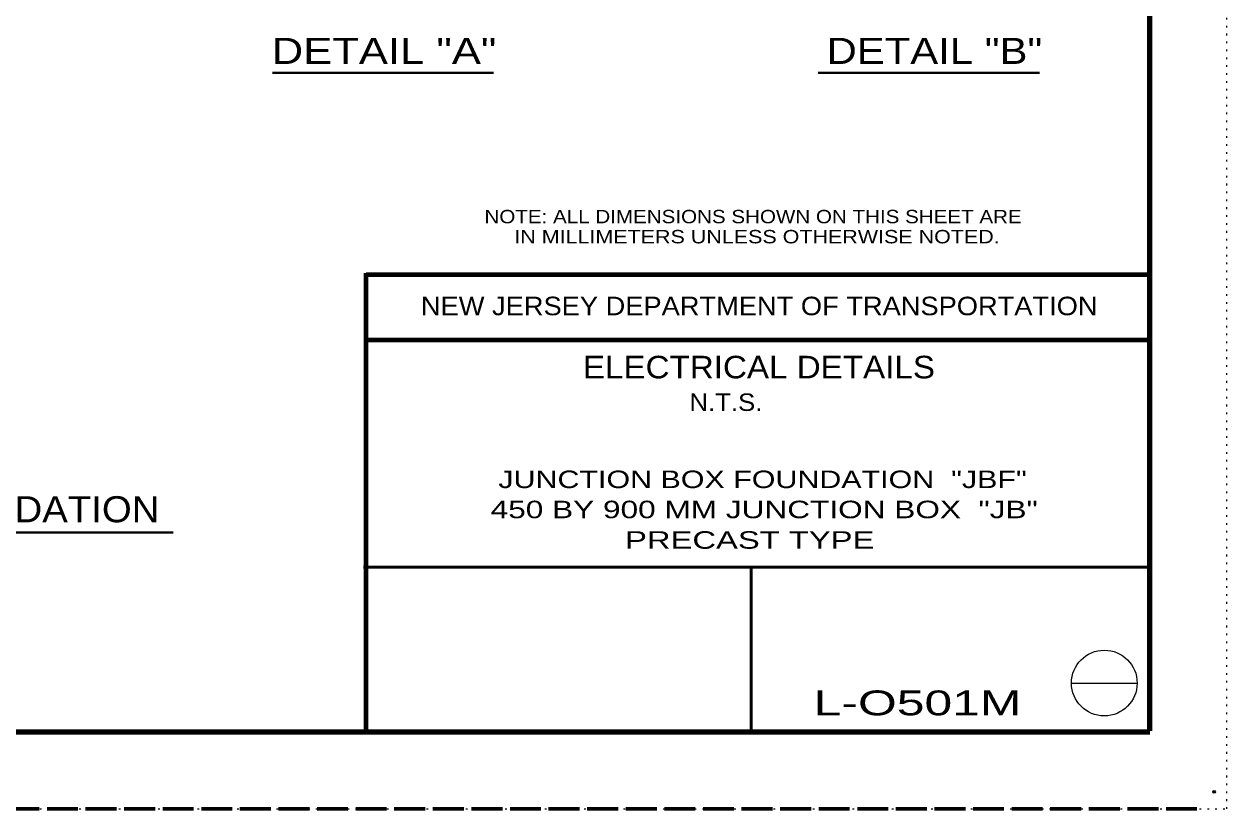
# Model space of a CAD drawing. Extents: x 312583 to 312854, y 144419 to 144597.
# Drawn here: x 312783.4 to 312853.5, y 144418.6 to 144464.3 of the extents above; entities that cross this region are included whole.
import ezdxf
from ezdxf.enums import TextEntityAlignment as Align

# ---------------------------------------------------------------- set-up
doc = ezdxf.new("R2010")
doc.units = 0
doc.header["$LTSCALE"] = 0.3
doc.header["$PDMODE"] = 32
doc.header["$PDSIZE"] = 0.15
doc.linetypes.add('DOTTED', pattern=[1.5, 0.3, -1.2])
doc.linetypes.add('LONG_DASHED', pattern=[7.5, 6, -1.5])
for name, color, linetype, lineweight in [('1', 7, 'Continuous', 25), ('10', 7, 'Continuous', 25), ('2', 7, 'Continuous', 13), ('63', 7, 'DOTTED', 13)]:
    doc.layers.add(name, color=color, linetype=linetype, lineweight=lineweight)
doc.layers.add('5', color=7, linetype='Continuous')

msp = doc.modelspace()

# ---------------------------------------------------------------- linework, layer by layer
at = {"layer": '1', "lineweight": 158}
for p, q in [((312849, 144423.1446), (312849, 144585.0846)), ((312616.5, 144423.0846), (312849, 144423.0846))]:
    msp.add_line(p, q, dxfattribs=at)
at = {"layer": '1', "lineweight": 80}
for p, q in [((312803.31, 144423.1446), (312803.31, 144449.8146)), ((312803.31, 144449.7246), (312849, 144449.7246)), ((312803.31, 144445.9146), (312849, 144445.9146))]:
    msp.add_line(p, q, dxfattribs=at)
at = {"layer": '1', "lineweight": 53}
for p, q in [((312849, 144432.6666), (312803.1533, 144432.6666)), ((312825.7547, 144432.6666), (312825.7547, 144423.1446))]:
    msp.add_line(p, q, dxfattribs=at)
at = {"layer": '1', "linetype": 'LONG_DASHED', "lineweight": 60}
msp.add_line((312851.75, 144418.5846), (312583.526, 144418.5846), dxfattribs=at)
at = {"layer": '1'}
msp.add_point((312852.75, 144419.5846), dxfattribs=at)
at = {"layer": '10'}
msp.add_line((312844.4383, 144425.9059), (312848.2793, 144425.9059), dxfattribs=at)
msp.add_circle((312846.3494, 144425.9205), 1.9159, dxfattribs=at)
at = {"layer": '2', "lineweight": 40}
for p, q in [((312797.8394, 144461.4821), (312810.7373, 144461.4821)), ((312829.6711, 144461.4821), (312842.569, 144461.4821)), ((312744.8632, 144434.7007), (312792.0611, 144434.7007))]:
    msp.add_line(p, q, dxfattribs=at)
at = {"layer": '63'}
msp.add_lwpolyline([(312601.2, 144418.5846), (312853.5, 144418.5846), (312853.5, 144596.7846)], dxfattribs=at)

# ---------------------------------------------------------------- texts
at = {"layer": '1'}
for s, width, p in [('NOTE: ALL DIMENSIONS SHOWN ON THIS SHEET ARE', 1.15, (312810.2073, 144452.7148)), ('     IN MILLIMETERS UNLESS OTHERWISE NOTED.', 1.2, (312810.2072, 144451.5448))]:
    msp.add_text(s, height=0.78, dxfattribs=dict(at, width=width)).set_placement(p)
at = {"layer": '1', "width": 1.1}
for s, height, p in [('NEW JERSEY DEPARTMENT OF TRANSPORTATION', 1.08, (312826.2285, 144447.3546)), ('ELECTRICAL DETAILS', 1.315, (312826.2109, 144443.6759))]:
    msp.add_text(s, height=height, dxfattribs=at).set_placement(p, align=Align.CENTER)
at = {"layer": '2'}
for s, height, width, p in [('DETAIL "A"', 1.52, 1.25, (312804.3525, 144461.9997)), ('DETAIL "B"', 1.52, 1.2, (312836.4455, 144461.9997)), ('    N.T.S.  ', 1.02, 1.1, (312823.87, 144441.778)), ('        JUNCTION BOX FOUNDATION  "JBF"       ', 1.02, 1.3, (312826.1764, 144437.2819)), ('ALTERNATE JUNCTION BOX FOUNDATION', 1.52, 1.1, (312768.3355, 144435.2893)), ('        450 BY 900 MM JUNCTION BOX  "JB"       ', 1.02, 1.35, (312826.2623, 144435.5263)), ('                PRECAST TYPE                ', 1.02, 1.4, (312825.6741, 144433.7476))]:
    msp.add_text(s, height=height, dxfattribs=dict(at, width=width)).set_placement(p, align=Align.CENTER)
at = {"layer": '5', "width": 1.5}
msp.add_text('L-O501M   ', height=1.449, dxfattribs=at).set_placement((312836.6707, 144424.0383), align=Align.CENTER)

doc.saveas('drawing.dxf')
